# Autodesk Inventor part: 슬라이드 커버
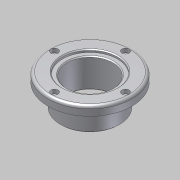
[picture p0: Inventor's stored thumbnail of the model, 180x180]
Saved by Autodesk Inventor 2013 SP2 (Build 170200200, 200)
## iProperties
Created: 2013-06
Part Number: 슬라이드 커버
Document SubType Name: Modeling
Designer: SeoGD™[esajin.kr]
Density: 1 g/cm^3
Material: 일반
Mass: 75.9731 g
Surface Area: 227.998 cm^2
Volume: 75.9731 cm^3
Author: SeoGD™[esajin.kr]
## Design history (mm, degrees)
sketch "스케치1"
  geometry: C1 r 46 at (0, -39.25) reference; C2 r 32.5 at (0, -39.25) reference; 1 further point
  node "참조1"
  node "참조2"
extrude "돌출1" new body sketch "스케치1" distance "d0" = 10; taper "d1" = 0 deg
extrude "돌출2" join sketch "스케치1" distance "d2" = 25; taper "d3" = 0 deg
hole "구멍1" diameter "d6" = 50; stored, may be unused: countersink angle "d10" = 90 deg, drill point angle "d12" = 118 deg; dims "d4" = 10, "d5" = 10, "d7" = 6, "d8" = 4, "d9" = 2, "d11" = 8
sketch "스케치2"
  geometry: C1 r 46 at (0, 0) reference; C2 r 1.621 at (0, 39) reference; C3 r 1.621 at (39, 0) reference; C4 r 1.621 at (0, -39) reference; C5 r 1.621 at (-39, 0) reference; C6 r 33.5 at (0, 0) reference; 1 further point
hole "구멍2" sketch "스케치2" at (0, 39) diameter "d13" = 4.5; stored, may be unused: countersink angle "d17" = 90 deg, drill point angle "d19" = 118 deg; dims "d14" = 6, "d15" = 8, "d16" = 4.4, "d18" = 8
fillet "모깎기1" dims "d23" = 3
chamfer "모따기1" distance "d24" = 1; stored, may be unused: second distance "d25" = 2, angle "d26" = 45 deg
sketch "스케치3"
  geometry: C1 r 25 at (39, 0) reference; C2 r 30 at (39, 0); 1 further point
  constraints: 1 centre point, 1 coincident
  dimensions: "d27" = 60 diameter of C2
extrude "돌출3" cut sketch "스케치3" distance "d28" = 3; taper "d29" = 0 deg
chamfer "모따기2" distance "d30" = 1; stored, may be unused: second distance "d31" = 2, angle "d32" = 45 deg
node "솔리드1"
pattern_circular "원형 패턴1" dims angle "d21" = 360 deg
node "참조3"
